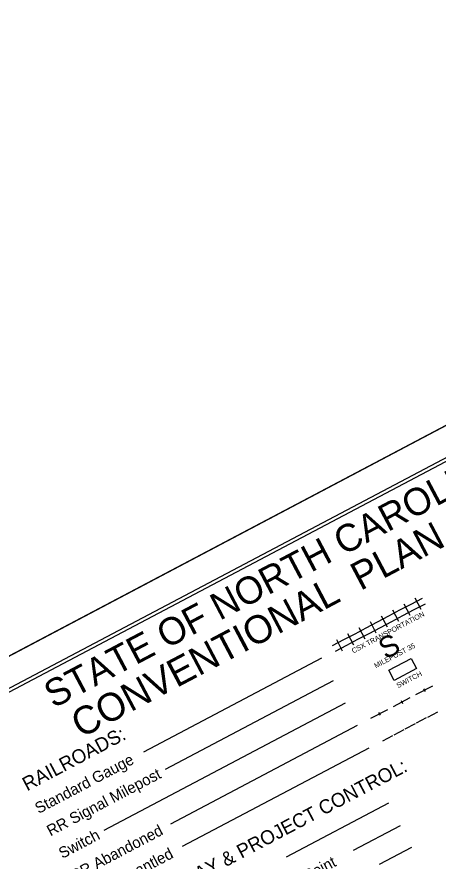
# Model space of a CAD drawing. Extents: x 1487118 to 1489121, y 496367 to 498126.
# Drawn here: x 1487660 to 1487992, y 497462 to 498126 of the extents above; entities that cross this region are included whole.
import ezdxf

# ---------------------------------------------------------------- set-up
doc = ezdxf.new("R2010")
doc.units = 0
for name, color, linetype in [('Sheet Cutting Line CELL', 7, 'Continuous'), ('Sheet Plot Border Inside CELL', 7, 'Continuous'), ('Sheet Plot Border Outside CELL', 7, 'Continuous'), ('Sheet Symbology CELL', 7, 'Continuous')]:
    doc.layers.add(name, color=color, linetype=linetype)

msp = doc.modelspace()

# ---------------------------------------------------------------- linework, layer by layer
at = {"layer": 'Sheet Cutting Line CELL'}
msp.add_line((1488607.16, 498126.35), (1487118.01, 497340.04), dxfattribs=at)
at = {"layer": 'Sheet Plot Border Inside CELL'}
msp.add_lwpolyline([(1487632.64, 496393.24), (1489106.32, 497171.37), (1488613.66, 498104.39), (1487139.99, 497326.26)], close=True, dxfattribs=at)
at = {"layer": 'Sheet Plot Border Outside CELL'}
msp.add_lwpolyline([(1487631.63, 496367.31), (1489120.78, 497153.62), (1488607.16, 498126.35), (1487118.01, 497340.04)], close=True, dxfattribs=at)
at = {"layer": 'Sheet Symbology CELL'}
for p, q in [((1487961.55, 497659.31), (1487970.4, 497663.98)), ((1487969.48, 497655.01), (1487964.81, 497663.85)), ((1487970.4, 497663.98), (1487979.24, 497668.65)), ((1487972.73, 497659.56), (1487981.58, 497664.22)), ((1487978.32, 497659.68), (1487973.65, 497668.52)), ((1487952.71, 497654.64), (1487961.55, 497659.31)), ((1487960.64, 497650.34), (1487955.97, 497659.18)), ((1487963.89, 497654.89), (1487972.73, 497659.56)), ((1487935.03, 497645.3), (1487943.87, 497649.97)), ((1487942.95, 497641), (1487938.28, 497649.85)), ((1487943.87, 497649.97), (1487952.71, 497654.64)), ((1487946.2, 497645.55), (1487955.05, 497650.22)), ((1487951.79, 497645.67), (1487947.12, 497654.51)), ((1487955.05, 497650.22), (1487963.89, 497654.89)), ((1487926.18, 497640.63), (1487935.03, 497645.3)), ((1487934.11, 497636.33), (1487929.44, 497645.18)), ((1487937.36, 497640.88), (1487946.2, 497645.55)), ((1487917.34, 497635.96), (1487926.18, 497640.63)), ((1487919.67, 497631.54), (1487928.52, 497636.21)), ((1487925.26, 497631.66), (1487920.59, 497640.51)), ((1487928.52, 497636.21), (1487937.36, 497640.88)), ((1487908.5, 497631.29), (1487917.34, 497635.96)), ((1487910.83, 497626.87), (1487919.67, 497631.54)), ((1487916.42, 497626.99), (1487911.75, 497635.84)), ((1487899.76, 497621.29), (1487759.68, 497547.33)), ((1487909.1, 497603.61), (1487776.85, 497533.78)), ((1487974.11, 497592.7), (1487987.37, 497599.7)), ((1487980.16, 497597.31), (1487981.32, 497595.1)), ((1487956.42, 497583.36), (1487969.69, 497590.37)), ((1487918.44, 497585.92), (1487728.39, 497485.57)), ((1487962.47, 497587.97), (1487963.64, 497585.76)), ((1487938.74, 497574.02), (1487952, 497581.03)), ((1487944.78, 497578.63), (1487945.95, 497576.42)), ((1487983.45, 497575.01), (1487991.41, 497579.22)), ((1487965.76, 497565.68), (1487973.72, 497569.88)), ((1487974.6, 497570.34), (1487982.56, 497574.55)), ((1487927.78, 497568.24), (1487780.84, 497490.65)), ((1487956.92, 497561.01), (1487964.88, 497565.21)), ((1487948.07, 497556.34), (1487956.03, 497560.54)), ((1487937.12, 497550.55), (1487790.18, 497472.96)), ((1487937.12, 497550.55), (1487790.18, 497472.96)), ((1487952.5, 497507.08), (1487872, 497464.58)), ((1487961.84, 497489.4), (1487924.77, 497469.82)), ((1487970.53, 497472.27), (1487945.28, 497458.93))]:
    msp.add_line(p, q, dxfattribs=at)
for points in [[(1488603.8, 498096.3), (1487277.36, 497395.91), (1487767.16, 496468.3), (1489093.6, 497168.69)], [(1487952.68, 497611.87), (1487970.36, 497621.21), (1487974.61, 497613.16), (1487956.92, 497603.83)]]:
    msp.add_lwpolyline(points, close=True, dxfattribs=at)

# ---------------------------------------------------------------- texts
for s, height, p in [('STATE OF NORTH CAROLINA, DIVISION OF HIGHWAYS', 21.419, (1487688.84, 497581.56)), ('CONVENTIONAL  PLAN SHEET SYMBOLS', 22.0323, (1487710.45, 497558.05)), ('CSX TRANSPORTATION', 4, (1487924.9, 497624.98)), ('S', 16.5, (1487950.31, 497620.14)), ('MILEPOST 35', 4, (1487942.58, 497613.32)), ('SWITCH', 4, (1487960.11, 497597.69)), ('RAILROADS:', 11, (1487668.04, 497516.41)), ('Standard Gauge', 8.75, (1487677.12, 497498.62)), ('RIGHT OF WAY & PROJECT CONTROL:', 11, (1487725.5, 497404.57)), ('RR Signal Milepost', 8.75, (1487686.46, 497480.93)), ('RR Abandoned', 8.75, (1487705.14, 497445.56)), ('Switch', 8.75, (1487695.8, 497463.24)), ('RR Dismantled', 8.75, (1487714.47, 497427.87)), ('Primary Horiz and Vert Control Point', 8.75, (1487744.88, 497369.69))]:
    msp.add_text(s, height=height, rotation=27.83509, dxfattribs=at).set_placement(p)

doc.saveas('drawing.dxf')
